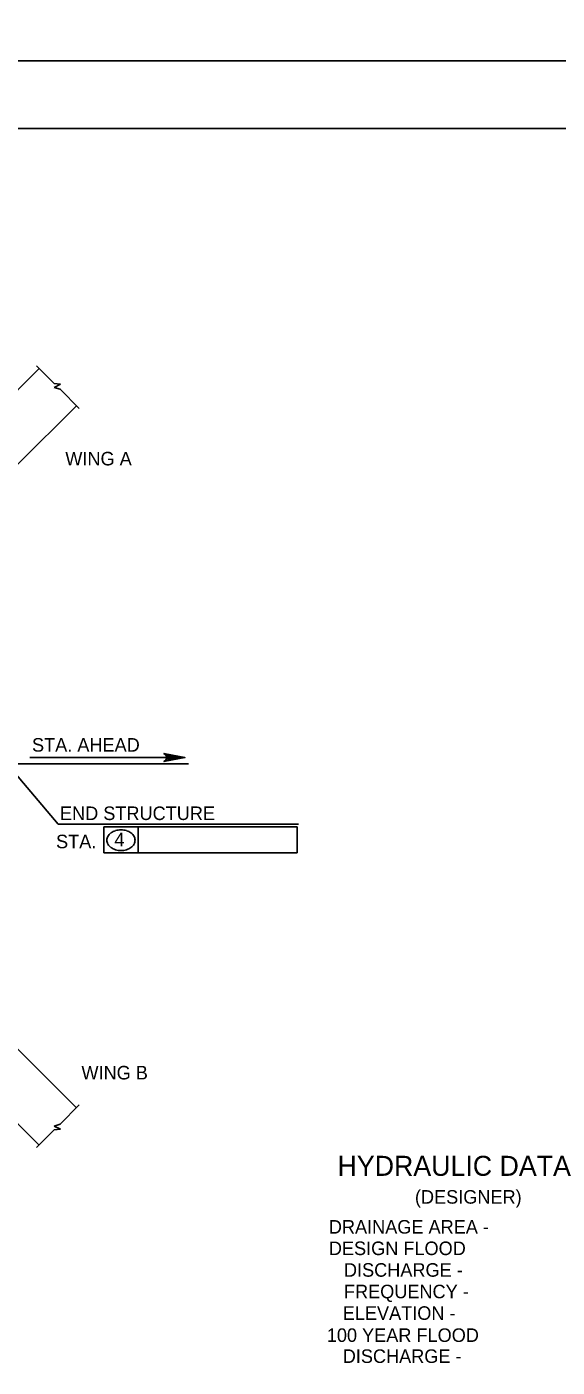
# Model space of a CAD drawing. Extents: x 638175 to 640495, y 294277 to 298435.
# Drawn here: x 638772.5 to 638889.9, y 297552.3 to 297849 of the extents above; entities that cross this region are included whole.
import ezdxf

# ---------------------------------------------------------------- set-up
doc = ezdxf.new("R2010")
doc.units = 0
for name, color, linetype in [('2', 7, 'Continuous'), ('3', 7, 'Continuous'), ('4', 7, 'Continuous'), ('PLT-BNDY', 7, 'Continuous')]:
    doc.layers.add(name, color=color, linetype=linetype)

msp = doc.modelspace()

# ---------------------------------------------------------------- linework, layer by layer
at = {"layer": '2'}
for p, q in [((638475.46, 297826.46), (639261.46, 297826.46)), ((638757.42, 297755.46), (638775.29, 297773.33)), ((638770.49, 297752.07), (638783.52, 297765.1)), ((638768.19, 297625.04), (638783.52, 297609.71)), ((638757.42, 297619.35), (638775.29, 297601.48))]:
    msp.add_line(p, q, dxfattribs=at)
at = {"layer": '3'}
for p, q in [((638778.61, 297770), (638774.7, 297773.91)), ((638779.97, 297769.84), (638778.57, 297769.14)), ((638778.57, 297769.14), (638779.88, 297768.73)), ((638778.61, 297770), (638779.97, 297769.84)), ((638784.15, 297764.46), (638779.88, 297768.73)), ((638784.15, 297610.35), (638779.88, 297606.08)), ((638778.61, 297604.81), (638774.7, 297600.9)), ((638778.57, 297605.67), (638779.88, 297606.08)), ((638779.97, 297604.97), (638778.57, 297605.67)), ((638778.61, 297604.81), (638779.97, 297604.97))]:
    msp.add_line(p, q, dxfattribs=at)
at = {"layer": '4'}
for p, q in [((638523.29, 297685.83), (638808.3, 297685.83)), ((638768.19, 297685.83), (638779.49, 297672.49)), ((638807.54, 297687.23), (638773.18, 297687.23)), ((638779.49, 297672.49), (638832.67, 297672.49)), ((638789.59, 297671.87), (638797.17, 297671.87)), ((638789.59, 297666.11), (638789.59, 297671.87)), ((638797.17, 297666.11), (638797.17, 297671.87)), ((638797.17, 297671.87), (638832.35, 297671.87)), ((638832.35, 297671.87), (638832.35, 297666.11)), ((638789.59, 297666.11), (638832.35, 297666.11))]:
    msp.add_line(p, q, dxfattribs=at)
msp.add_lwpolyline([(638807.54, 297687.23), (638802.88, 297686.36), (638803.24, 297686.61), (638803.43, 297686.92), (638803.48, 297687.23), (638803.43, 297687.55), (638803.24, 297687.86), (638802.88, 297688.11), (638807.54, 297687.23), (638803.24, 297687.86), (638803.43, 297687.55), (638807.54, 297687.23), (638803.48, 297687.23), (638803.43, 297686.92), (638807.54, 297687.23), (638803.24, 297686.61)], dxfattribs=at)
for centre, radius, start, end in [((638792.64, 297668.56), 2.49, 126.3544, 150.6308), ((638793.08, 297667.96), 3.23, 106.9552, 126.3544), ((638793.37, 297667.02), 4.22, 90, 106.9552), ((638793.37, 297667.02), 4.22, 73.0448, 90), ((638793.66, 297667.96), 3.23, 53.6456, 73.0448), ((638794.1, 297668.56), 2.49, 29.3692, 53.6456), ((638791.97, 297668.94), 1.71, 150.6308, 180), ((638791.97, 297668.94), 1.71, 180, 209.3692), ((638792.64, 297669.32), 2.49, 209.3692, 233.6456), ((638793.08, 297669.92), 3.23, 233.6456, 253.0448), ((638793.37, 297670.87), 4.22, 253.0448, 270), ((638793.37, 297670.87), 4.22, 270, 286.9552), ((638793.66, 297669.92), 3.23, 286.9552, 306.3544), ((638794.1, 297669.32), 2.49, 306.3544, 330.6308), ((638794.78, 297668.94), 1.71, 0, 29.3692), ((638794.78, 297668.94), 1.71, 330.6308, 0)]:
    msp.add_arc(centre, radius, start, end, dxfattribs=at)
at = {"layer": 'PLT-BNDY'}
for points in [[(638435.46, 298435.46), (639276.46, 298435.46), (639276.46, 297841.46), (638435.46, 297841.46)], [(638435.46, 297841.46), (639276.46, 297841.46), (639276.46, 297247.46), (638435.46, 297247.46)]]:
    msp.add_lwpolyline(points, close=True, dxfattribs=at)

# ---------------------------------------------------------------- texts
at = {"layer": '4'}
for s, height, p in [('WING A', 3, (638781.05, 297751.89)), ('STA. AHEAD', 3, (638773.68, 297688.54)), ('END STRUCTURE', 3, (638779.87, 297673.4)), ('STA.', 3, (638779, 297667.16)), ('4', 3, (638791.92, 297667.59)), ('WING B', 3, (638784.62, 297615.99)), ('HYDRAULIC DATA', 4.4292, (638841.31, 297594.66)), ('(DESIGNER)', 3, (638858.45, 297588.5)), ('DRAINAGE AREA - ', 3, (638839.39, 297581.87)), ('DESIGN FLOOD  ', 3, (638839.39, 297577.12)), ('   DISCHARGE - ', 3, (638839.39, 297572.33)), ('   FREQUENCY - ', 3, (638839.39, 297567.56)), ('   ELEVATION - ', 3, (638839.12, 297562.79)), ('100 YEAR FLOOD', 3, (638838.94, 297557.9)), ('   DISCHARGE - ', 3, (638839.12, 297553.25))]:
    msp.add_text(s, height=height, dxfattribs=at).set_placement(p)

doc.saveas('drawing.dxf')
